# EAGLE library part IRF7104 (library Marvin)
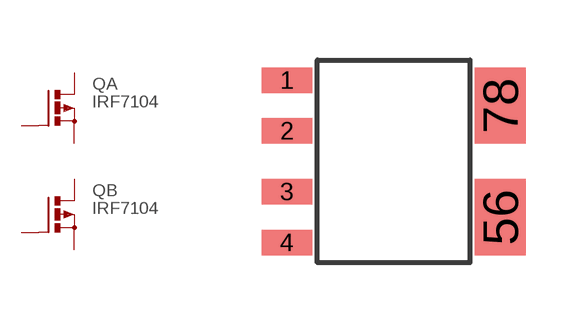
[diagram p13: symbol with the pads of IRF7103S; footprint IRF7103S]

Designator prefix Q; gates A=MFP B=MFP

## IRF7104S  [IRF7103S]
1  A:S  pas
2  A:G  pas
3  B:S  pas
4  B:G  pas
56  B:D  pas
78  A:D  pas

## Footprint IRF7103S (pad centres in mm)
smd 1.27 x 0.635: 1 -2.794,2.032; 2 -2.794,0.762; 3 -2.794,-0.762; 4 -2.794,-2.032
smd 1.27 x 1.905: 56 2.54,-1.397; 78 2.54,1.397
